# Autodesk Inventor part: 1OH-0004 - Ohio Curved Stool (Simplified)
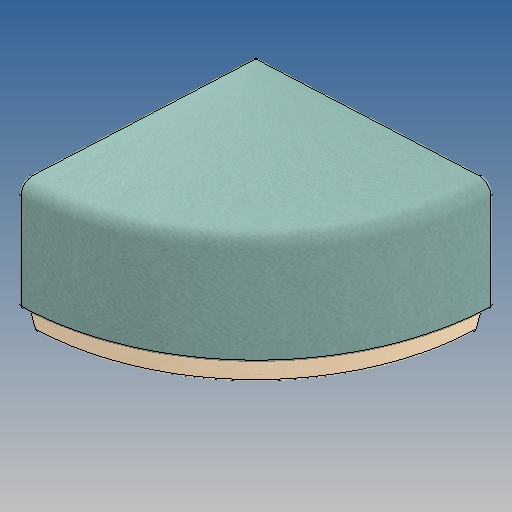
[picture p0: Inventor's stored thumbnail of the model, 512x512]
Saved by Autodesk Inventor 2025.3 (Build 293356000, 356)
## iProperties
Created: 2025-11
Part Number: 1OH-0004 - Ohio Curved Stool (Simplified)
Material: Generic
Document SubType Name: Modeling
Designer: craig.ferris
Density: 1 g/cm^3
Appearance: CADET-ZEST SEAFOAM (219)
Author: craig.ferris
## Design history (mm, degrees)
derived "1OH-0004 - Ohio Curved Stool (Rev D) - Enclosed Plinth - Uph"
body "Solid1"
body "Solid2"
body "Solid3"
body "Solid4"
body "Solid5"
body "Solid6"
body "Solid7"
body "Solid8"
